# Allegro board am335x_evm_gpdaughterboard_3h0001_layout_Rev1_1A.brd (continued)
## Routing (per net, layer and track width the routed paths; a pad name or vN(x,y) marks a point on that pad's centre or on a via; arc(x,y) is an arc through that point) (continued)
VDDSHV5: length 1.9
  TOP w0.121: R4.2 R8.2
VDDSHV6: length 16.9
  TOP w0.254: U2.24 v1(112.15,97.42) ; U2.1 121.35,94.89 v1(121.46,94.78) ; v1(119.04,89.06) 118.95,89.15 U2.42 ; U2.31 v1(114.55,91.99)
  TOP w0.305: U11.3 v1(60.55,78.71) ; U10.3 v1(60.43,83.28)
  TOP w0.381: 60.38,83.22 v1(60.43,83.28)
  TOP w0.635: v1(60.49,76.24) 60.87,75.86 R9.2 v1(59.61,75.1) ; v1(62.78,76.24) R5.2 v1(63.78,75.1) ; C40.1 60.38,83.22
  BOTTOM w0.635: v1(60.55,78.71) 60.62,78.78 C44.1 ; v1(119.04,89.06) 119.23,89.25 119.23,89.35 119.29,89.42 C14.1 ; C13.1 114.55,91.56 v1(114.55,91.99)
ACCEL_INT1: length 55.8
  TOP w0.121: v2(93.34,67.13) U43.L5 ; U9.11 78.9,93.26 79.39,92.77 v1(79.39,92.75)
  LY3 w0.102: v2(93.34,67.13) 93.41,67.13 93.89,67.6 94.53,67.6 94.78,67.86 94.78,68.36 94.44,68.7 88.81,68.7
  LY3 w0.121: v1(79.39,92.75) 79.83,92.31 79.83,71.1 82.22,68.7 88.81,68.7
ACCEL_INT2: length 53.8
  TOP w0.121: U9.9 65.12,92.26 v1(65.43,91.94) ; v2(94.34,67.13) U43.L6
  LY3 w0.121: v1(66.91,68.3) 66.91,78 65.43,79.47 v1(65.43,91.94)
  LY6 w0.102: 88.81,68.11 92.64,68.11 93.03,67.72 93.74,67.72 v2(94.34,67.13)
  LY6 w0.121: v1(66.91,68.3) 71.6,68.3 71.79,68.11 88.81,68.11
AM335X_ECAP0_IN_PWM0_OUT: length 65.8
  TOP w0.121: v2(101.34,77.13) U43.B12
  LY3 w0.102: v2(98.64,94.7) 98.51,94.83 98.51,95.76 98.55,95.8 98.55,98.88 97.7,99.73 97.7,102.24 97.35,102.6 97.35,102.96 97.61,103.22
  LY3 w0.121: J3.19 96.43,135.75 98.71,133.47 98.71,125.17 97.02,123.47 97.02,118.39 98.15,117.26 98.15,103.76 97.61,103.22
  LY6 w0.102: v2(101.34,77.13) 101.34,77.55 101.26,77.63 101.26,79.13
  LY6 w0.121: v1(99.34,84.05) 100.93,84.05 101.26,83.73 101.26,79.13
  BOTTOM w0.102: v2(98.64,94.7) 98.51,94.58 98.51,94.21
  BOTTOM w0.121: 98.51,94.21 98.51,84.87 v1(99.34,84.05)
AM335X_GPMC_A0: length 141.4
  TOP w0.102: 97.73,78.65 98.04,78.34 98.1,78.34 98.23,78.21 98.23,75.44 97.84,75.04 U43.D9
  TOP w0.121: v1(86.94,82.28) 87.06,82.28 87.25,82.47 90.33,82.47 93.07,79.73 96.64,79.73 97.73,78.65 ; J4.2 83.73,128.18 83.86,128.31 83.86,129.58 83.73,129.7 81.32,129.7 81.19,129.58 81.19,127.67 81.06,127.55 73.71,127.55 73.58,127.67 73.58,129.97 73.46,130.09 73.22,130.09 73.1,129.97 73.1,127.67 72.98,127.55 72.74,127.55 72.62,127.67 72.62,129.97 72.5,130.09 72.26,130.09 72.14,129.97 72.14,127.67 72.02,127.55 71.77,127.55 71.65,127.67 71.65,129.97 71.53,130.09 71.29,130.09 71.17,129.97 71.17,127.67 71.05,127.55 70.81,127.55 70.69,127.67 70.69,129.97 70.57,130.09 70.33,130.09 70.21,129.97 70.21,127.67 70.09,127.55 69.63,127.55 69.51,127.67 69.51,130.95 69.38,131.07 67.42,131.07 67.3,131.2 67.3,133.51 67.17,133.64 66.94,133.64 66.82,133.51 66.82,131.2 66.7,131.07 66.45,131.07 66.33,131.2 66.33,132 66.21,132.12 65.97,132.12 65.85,132 65.85,131.2 65.73,131.07 65.49,131.07 65.37,131.2 65.37,132 65.25,132.12 65.01,132.12 64.89,132 64.89,131.2 64.77,131.07 64.52,131.07 64.4,131.2 64.4,131.86 64.28,131.99 64.05,131.99 63.92,131.86 63.92,131.36 v1(63.65,131.09)
  LY6 w0.121: v1(75.03,82.47) 75.22,82.28 v1(86.94,82.28)
  BOTTOM w0.121: v1(63.65,131.09) 66.96,127.78 66.96,105.21 68.34,103.83 68.34,86.17 68.66,85.86 71.65,85.86 v1(75.03,82.47)
AM335X_GPMC_A1: length 63.3
  TOP w0.121: v2(99.34,75.12) U43.D10
  LY3 w0.102: v2(99.34,75.12) 98.97,75.12 98.07,76.03 98.07,78.65
  LY3 w0.121: v1(95.92,116.82) 95.92,116.24 96.29,115.87 96.29,113.53 95.71,112.95 95.71,100.7 96.22,100.2 96.22,96.26 96.68,95.8 96.68,93.13 97.62,92.19 97.62,89.39 98.07,88.95 98.07,78.65
  LY6 w0.121: v1(95.92,116.82) 91.03,116.82 86.27,121.58 86.27,126.91 J4.4
AM335X_GPMC_A2: length 63.2
  TOP w0.121: v2(100.34,75.12) U43.D11
  LY3 w0.102: 98.34,78.65 98.34,76.24 98.97,75.6 99.86,75.6 100.34,75.13 v2(100.34,75.12)
  LY3 w0.121: 98.34,78.65 98.34,89.17 97.9,89.6 97.9,92.42 96.94,93.38 96.94,96.43 96.46,96.9 96.46,100.46 96.18,100.75 96.18,113.07 96.54,113.43 96.54,116.94 95.96,117.52 v1(95.93,117.52)
  LY6 w0.121: v1(95.93,117.52) 95.93,117.52 95.47,117.06 91.42,117.06 88.56,119.93 88.56,127.16 J4.6
AM335X_GPMC_A3: length 63.1
  TOP w0.121: v2(101.34,75.12) U43.D12
  LY3 w0.121: v1(99.03,116.94) 99.22,116.75 99.22,106.97 101.64,104.56 101.64,100.62 101.99,100.27 101.99,92.72 101.58,92.31 101.58,90.21 101.64,90.15 v1(101.64,85.13)
  LY6 w0.102: 101.64,78.65 101.64,78.27 101.94,77.96 101.94,76.15 101.34,75.54 v2(101.34,75.12)
  LY6 w0.121: v1(101.64,85.13) 101.64,78.65 ; J4.8 90.08,128.05 91.22,126.91 91.22,118.53 91.99,117.77 95.29,117.77 95.54,118.02 97.95,118.02 v1(99.03,116.94)
AM335X_GPMC_A4: length 101.3
  TOP w0.121: v1(112.33,130.49) 111.8,129.96 99.68,129.96 98.87,129.15 93.89,129.15 92.92,128.18 J4.10 ; U43.D13 v2(102.33,75.12) ; U4.41 v1(118.55,105.6)
  LY6 w0.102: v2(102.33,75.12) 102.33,75.54 102.73,75.94 102.73,78.29 102.44,78.58 102.44,78.65
  LY6 w0.121: v1(120.66,85.86) 120.33,85.53 113.98,85.53 113.34,86.17 104.92,86.17 102.44,83.7 102.44,78.65 ; v1(112.33,130.49) 112.33,130.11 111.82,129.6 111.82,119.44 118.3,112.97 118.3,108.67 118.55,108.42 v1(118.55,105.6)
  BOTTOM w0.121: v1(118.55,105.6) 118.55,104.74 118.86,104.43 118.86,104.43 119.16,104.13 119.16,104.13 119.67,103.62 119.67,99.33 120.59,98.41 120.59,97.26 120.57,97.24 120.57,92.2 120.48,92.11 120.48,90.18 120.99,89.67 120.99,86.19 v1(120.66,85.86)
AM335X_GPMC_A5: length 171
  TOP w0.121: U4.40 118.15,102 117.39,101.24 109.33,101.24 v1(109.14,101.43) 108.5,102.07 108.5,103.92 107.73,104.69 98.84,104.69 98.24,105.29 92.67,105.29 91.91,106.05 68.97,106.05 68.49,105.57 66.49,105.57 v1(66.01,106.05) ; U43.D14 v2(103.33,75.12) ; v1(66.03,135.29) 67.04,134.28 67.73,134.28 67.98,134.02 67.98,131.86 68.24,131.61 69.76,131.61 70.14,131.23 70.14,130.85 70.4,130.59 76.36,130.59 76.49,130.47 76.49,128.43 76.62,128.31 76.87,128.31 76.99,128.43 76.99,130.22 77.11,130.34 77.35,130.34 77.47,130.22 77.47,128.43 77.59,128.31 77.83,128.31 77.95,128.43 77.95,130.22 78.07,130.34 78.31,130.34 78.43,130.22 78.43,128.43 78.55,128.31 78.8,128.31 78.92,128.43 78.92,130.22 79.04,130.34 79.28,130.34 79.4,130.22 79.4,128.43 79.52,128.31 80.43,128.31 80.56,128.43 80.56,130.85 80.68,130.97 88.76,130.97 88.88,130.85 88.88,127.68 89.06,127.5 89.58,126.98 95.03,126.98 95.16,127.11 J4.12
  LY3 w0.121: v1(109.14,101.43) 109.58,100.99 109.58,84.1 109.33,83.85 109.33,82.66 109.38,82.61 v1(109.38,80.14) ; v1(66.03,135.29) 66.01,135.28 v1(66.01,106.05)
  LY6 w0.102: v2(103.33,75.12) 103.94,75.73 104.5,75.73 104.73,75.96 104.73,76.67 104.93,76.88 104.93,77.35 105.22,77.63 105.52,77.63 105.85,77.96 105.85,78.62 105.89,78.65
  LY6 w0.121: 105.89,78.65 107.38,80.14 v1(109.38,80.14)
AM335X_GPMC_A6: length 229.2
  TOP w0.121: U43.E6 v2(94.34,74.12) ; U4.38 117.35,104.18 117.27,104.26 v1(117.27,104.99) ; J4.16 99.16,127.1 96.16,127.1 95.8,126.74 89.48,126.74 88.56,127.66 88.56,129.7 87.92,130.34 80.94,130.34 80.81,130.21 80.81,128.18 80.68,128.05 76.3,128.05 76.18,128.17 76.18,130.22 76.06,130.34 75.82,130.34 75.7,130.22 75.7,128.05 75.57,127.93 75.34,127.93 75.21,128.05 75.21,130.22 75.09,130.34 74.85,130.34 74.73,130.22 74.73,128.18 74.6,128.05 74.38,128.05 74.25,128.18 74.25,130.22 74.13,130.34 70.01,130.34 69.76,130.59 69.76,131.1 69.51,131.36 67.98,131.36 67.6,131.74 67.6,133.64 67.35,133.9 63.97,133.9 v1(63.07,134.8)
  LY3 w0.102: v2(94.34,74.12) 93.73,74.73 93.06,74.73 92.93,74.86 92.93,75.42 92.62,75.73 92.37,75.73 92.37,75.72 92.18,75.72 91.94,75.96 91.94,76.44 91.65,76.73 91.08,76.73 90.74,77.07 90.74,78.65
  LY3 w0.121: v1(63.07,134.8) 64.3,133.56 v1(64.3,111.73) ; v1(80.45,135.92) 80.45,113.91 81.15,113.21 81.15,86.32 82.53,84.94 84.03,84.94 84.54,85.46 85.95,85.46 86.45,84.96 86.45,84.28 88.26,82.47 89.66,82.47 90.2,81.93 90.2,81.5 90.86,80.85 90.86,78.77 90.74,78.65
  LY6 w0.121: v1(80.45,135.92) 79.33,134.8 v1(63.07,134.8) ; v1(117.27,104.99) 113,109.26 95.76,109.26 93.55,111.46 73.78,111.46 73.06,112.18 64.75,112.18 v1(64.3,111.73)
AM335X_GPMC_A7: length 101.2
  TOP w0.121: v2(95.34,74.12) U43.E7 ; U4.37 116.95,101.96 v1(116.75,101.76) ; J4.18 104.27,129.67 118.39,129.67 v1(118.43,129.63)
  LY3 w0.102: v2(95.34,74.12) 95.93,74.72 95.93,78.58 95.91,78.58 95.88,78.61 95.88,78.65
  LY3 w0.121: 95.88,78.65 95.88,95.16 95.47,95.57 95.47,99.54 94.65,100.37 v1(94.65,102.78)
  LY6 w0.121: v1(116.75,101.76) 115.61,101.76 114.81,102.56 108.02,102.56 106.4,104.18 96.05,104.18 v1(94.65,102.78)
  BOTTOM w0.121: v1(116.75,101.76) 116.58,101.93 116.58,105.27 116.88,105.58 116.88,109.46 116.58,109.77 116.58,109.81 115.99,110.4 115.99,119.04 115.73,119.29 115.73,122.08 118.43,124.78 118.43,129.32 118.43,129.33 v1(118.43,129.63)
AM335X_GPMC_A8: length 98.8
  TOP w0.121: J4.22 107.86,128.15 109.31,126.71 v1(121.98,126.71) ; U4.47 120.95,104.11 121.27,104.43 v1(122.53,104.43) ; v2(96.34,74.12) U43.E8
  LY6 w0.102: v2(96.34,74.12) 96.34,73.71 96.73,73.31 96.73,73.13 97.13,72.73 97.68,72.73 98.25,73.3 98.25,78.65
  LY6 w0.121: 98.25,78.65 98.25,85.2 99.47,86.42 113.44,86.42 113.98,85.89 119.97,85.89 123.79,89.7 123.79,103.19 122.54,104.43 v1(122.53,104.43) 122.53,105.28 122.46,105.35 122.46,107.62 122.53,107.68 122.53,108.04 122.46,108.1 122.46,126.22 v1(121.98,126.71)
AM335X_GPMC_A9: length 93.9
  TOP w0.121: U4.46 120.55,104.19 121.37,105.02 v1(122.01,105.02) ; J4.24 111.52,129.3 116.8,129.3 117.39,128.71 v1(119.29,128.71) ; v2(97.34,74.12) U43.E9
  LY6 w0.102: v2(97.34,74.12) 97.67,74.12 98,74.46 98,78.52 97.88,78.65
  LY6 w0.121: 97.88,78.65 97.88,85.51 99.1,86.73 113.48,86.73 114.08,86.13 119.84,86.13 123.42,89.71 123.42,102.89 122.01,104.3 v1(122.01,105.02) 121.53,105.5 121.53,112.08 118.96,114.64 118.96,128.38 v1(119.29,128.71)
AM335X_GPMC_A10: length 86.3
  TOP w0.102: 106.91,103.01 107.5,102.42
  TOP w0.121: v1(99.59,103.67) 100.96,103.67 101.6,103.04 106.88,103.04 106.91,103.01 ; v1(120.15,105.55) 120.15,105.49 119.65,104.99 119.65,104.28 119.75,104.17 U4.44 119.75,101.81 118.86,100.93 108.99,100.93 107.5,102.42 ; v2(99.34,74.12) U43.E10 ; v1(120,127.27) 119.57,127.27 119.37,127.06 114.01,127.06 112.94,128.13 J4.26
  LY3 w0.102: 99.59,103.01 99.59,95.07 99.33,94.82 99.33,94.48 99.54,94.28 99.54,94.21
  LY3 w0.121: v1(99.69,80.68) 99.69,81.19 99.88,81.38 99.88,92.7 99.54,93.04 99.54,94.21 ; v1(99.59,103.67) 99.59,103.01
  LY6 w0.102: v2(99.34,74.12) 99.34,74.54 99.74,74.95 99.74,78.65
  LY6 w0.121: v1(99.69,80.68) 99.69,80.31 99.85,80.14 99.85,79.06 99.74,78.95 99.74,78.65
  BOTTOM w0.121: v1(120,127.27) 120,109.26 119.65,108.9 119.65,107.35 120.15,106.85 v1(120.15,105.55)
AM335X_GPMC_A11: length 83.9
  TOP w0.121: v2(100.34,74.12) U43.E11 ; U4.43 v1(119.35,105.57)
  LY3 w0.102: 107.86,69.82 107.71,69.67 105.09,69.67 104.71,70.05 v1(104.34,70.05)
  LY3 w0.121: 107.86,69.82 108.24,70.2 110.97,70.2 111.31,69.87 v1(111.75,69.87) ; v1(116.39,120.67) 116.39,125.21 116.43,125.25 116.43,127.23 J4.28
  BOTTOM w0.102: v1(104.34,70.05) 103.85,70.53 101.33,70.53 100.93,70.93 100.93,72.25 100.49,72.68 100.11,72.68 99.86,72.94 99.86,73.65 v2(100.34,74.12)
  BOTTOM w0.121: v1(111.75,69.87) 111.75,70.52 121.39,80.16 121.39,92.14 120.82,92.72 120.82,97.14 120.84,97.16 120.84,98.54 119.95,99.43 119.95,103.8 119.35,104.41 v1(119.35,105.57) 119.35,109.78 119.48,109.91 119.48,110.38 119.35,110.51 119.35,117.71 v1(116.39,120.67)
AM335X_GPMC_AD0: length 111.7
  TOP w0.121: v1(95.22,142.72) U23.6
  LY3 w0.121: v1(34.33,142.28) 34.77,141.84 34.77,141.21 34.33,140.76 34.33,128.43 32.68,126.78 31.91,126.78 31.34,126.21 31.34,117.25 31.83,116.75 31.83,104.56 31.96,104.43 32.55,104.43 32.68,104.56 32.68,105.19 32.8,105.32 35.09,105.32 35.22,105.19 35.22,104.18 35.09,104.05 J1.17
  LY6 w0.121: v1(34.33,142.28) 35.16,142.28 35.34,142.46 80.85,142.46 81.54,141.77 87.28,141.77 87.41,141.9 87.41,142.59 87.54,142.72 89.95,142.72 90.08,142.59 90.08,141.9 90.21,141.77 90.59,141.77 90.72,141.9 90.72,142.59 90.84,142.72 92.87,142.72 93,142.59 93,142.15 93.13,142.02 93.51,142.02 93.64,142.15 93.64,142.59 93.76,142.72 v1(95.22,142.72)
AM335X_GPMC_AD1: length 112.6
  TOP w0.121: U23.7 v1(96.16,143.44)
  LY3 w0.121: v1(34.33,143.04) 35.02,142.35 35.02,141.03 34.9,140.92 34.9,128.63 31.59,125.31 31.59,117.79 32.43,116.95 32.43,111.57 33.18,110.81 33.18,108.62 33.69,108.11 34.71,108.11 35.09,107.73 37.76,107.73 37.88,107.61 37.88,105.32 37.76,105.19 35.6,105.19 J1.15
  LY6 w0.121: v1(96.16,143.44) 95,143.44 94.54,142.98 86.95,142.98 85.88,144.06 75.98,144.06 74.97,143.04 36.86,143.04 36.72,143.17 36.3,143.17 36.13,143.35 35.44,143.35 35.13,143.04 v1(34.33,143.04)
AM335X_GPMC_AD2: length 112.5
  TOP w0.121: v1(91.73,141.9) 92,142.17 U23.1
  LY3 w0.121: J1.13 35.34,107.99 37.63,107.99 37.76,108.11 37.76,110.34 37.63,110.46 33.88,110.46 32.68,111.67 32.68,117.05 31.84,117.89 31.84,123.53 32.93,124.62 32.93,126.02 33.18,126.28 37.76,126.28 39.03,127.55 39.03,130.59 38.77,130.85 38.14,130.85 38.01,130.97 38.01,131.74 38.14,131.86 38.9,131.86 39.03,131.99 39.03,135.17 38.9,135.29 38.26,135.29 38.14,135.42 38.14,136.31 38.26,136.44 38.9,136.44 39.03,136.56 39.03,138.59 38.9,138.72 35.85,138.72 35.15,139.42 35.15,140.82 35.64,141.3 v1(35.64,141.83)
  LY6 w0.121: v1(91.73,141.9) 91.22,141.9 90.79,141.47 81.58,141.47 81.55,141.5 81.46,141.5 80.81,142.14 78.77,142.14 78.77,142.15 78.4,142.15 78.4,142.14 37.62,142.14 37.56,142.21 37.19,142.21 37.13,142.14 35.95,142.14 v1(35.64,141.83)
AM335X_GPMC_AD3: length 112.5
  TOP w0.121: v1(92.49,141.01) 93,141.52 U23.3
  LY3 w0.121: J1.11 35.6,111.67 35.72,111.8 35.72,113.07 35.6,113.19 33.06,113.19 32.93,113.32 32.93,117.64 32.79,117.78 32.3,117.78 32.17,117.91 32.17,123.48 32.3,123.61 33.06,123.61 33.18,123.74 33.18,125.77 33.31,125.89 37.63,125.89 37.76,125.77 37.76,123.86 37.88,123.74 38.52,123.74 38.65,123.86 38.65,126.5 39.28,127.13 39.28,138.72 39.03,138.98 35.98,138.98 35.62,139.34 v1(35.62,140.56)
  LY6 w0.121: v1(92.49,141.01) 92.49,139.05 91.53,138.09 71.92,138.09 71.79,138.21 71.79,139.66 71.67,139.79 71.03,139.79 70.9,139.66 70.9,138.98 70.78,138.85 69.89,138.85 69.76,138.98 69.76,139.66 69.63,139.79 35.74,139.79 35.62,139.92 v1(35.62,140.56)
AM335X_GPMC_AD4: length 108.8
  TOP w0.121: R255.2 83.67,143.61 v1(83.48,143.61)
  LY3 w0.121: J1.9 35.47,114.21 35.6,114.34 35.6,115.61 35.47,115.73 33.38,115.73 33.25,115.86 33.25,118.02 33.12,118.15 32.55,118.15 32.42,118.27 32.42,123.23 32.55,123.35 38.52,123.35 38.9,123.74 38.9,126.4 39.53,127.04 39.53,146.98 39.41,147.1 38.26,147.1 38.14,146.98 38.14,143.29 38.4,143.03 38.62,143.03 38.89,142.76 38.89,139.76 38.49,139.36 36.49,139.36 36.11,139.74 36.11,142.53 35.73,142.91 v1(35.72,142.91)
  LY6 w0.121: v1(35.72,142.91) 36.42,142.91 36.61,142.72 75.41,142.72 76.3,143.61 v1(83.48,143.61)
AM335X_GPMC_AD5: length 107
  TOP w0.121: R257.2 86.07,144.26 v1(86.7,144.26)
  LY3 w0.121: v1(36.49,143.61) 36.49,142.72 36.35,142.59 36.35,139.86 36.48,139.74 38.52,139.74 38.65,139.86 38.65,142.66 38.52,142.79 38,142.79 37.88,142.91 37.88,147.74 38,147.87 39.67,147.87 39.79,147.74 39.79,126.78 39.67,126.66 39.53,126.66 39.17,126.29 39.17,123.37 38.9,123.1 32.94,123.1 32.81,122.97 32.81,119.03 33.69,118.15 34.07,118.15 34.2,118.02 J1.7
  LY6 w0.121: v1(86.7,144.26) 86.21,144.26 86.02,144.45 75.22,144.45 74.07,143.29 38.26,143.29 37.94,143.61 v1(36.49,143.61)
AM335X_GPMC_AD6: length 98.5
  TOP w0.121: R256.2 78.4,144.56 77.63,143.8 v1(77.63,141.7)
  LY3 w0.121: v1(37.38,141.77) 36.87,141.77 36.74,141.64 36.74,140.37 36.87,140.25 38.26,140.25 38.39,140.37 38.39,142.4 38.26,142.53 37.76,142.53 37.63,142.66 37.63,149.64 37.76,149.77 39.92,149.77 40.04,149.64 40.04,126.53 39.78,126.27 39.69,126.27 39.41,126 39.41,123.1 39.16,122.85 33.18,122.85 33.06,122.72 33.06,119.42 33.18,119.29 J1.5
  LY6 w0.121: v1(77.63,141.7) 40.62,141.7 40.55,141.77 v1(37.38,141.77)
AM335X_GPMC_AD7: length 97.5
  TOP w0.121: v1(80.05,141.13) 80.05,143.89 80.68,144.52 R258.2
  LY3 w0.121: J1.3 34.2,120.43 34.33,120.31 39.53,120.31 39.66,120.43 39.66,125.89 39.79,126.02 40.17,126.02 40.3,126.15 40.3,150.28 40.17,150.41 37.5,150.41 37.38,150.28 37.38,142.4 37.5,142.28 38.01,142.28 38.14,142.15 38.14,141.01 38.01,140.88 v1(37.38,140.88)
  LY6 w0.121: v1(37.38,140.88) 39.53,140.88 39.65,141 79.53,141 79.67,141.13 v1(80.05,141.13)
AM335X_GPMC_AD8: length 107.9
  TOP w0.121: v2(103.33,63.13) U43.R14
  LY3 w0.102: 103.16,59.6 102.94,59.82 102.94,62.3 103.33,62.69 v2(103.33,63.13) ; 34.91,80.17 J5.11
  LY3 w0.121: v1(103.16,51.6) 103.16,53.8 102.99,53.97 102.99,55.59 102.85,55.73 102.85,56.1 103.16,56.41 103.16,59.6 ; v1(38.14,53.5) 38.14,65.19 35.47,67.86 35.47,79.79 35.09,80.17 34.91,80.17
  LY6 w0.121: v1(38.14,53.5) 38.57,53.94 41.51,53.94 42.58,52.87 57.31,52.87 58.33,51.85 102.4,51.85 102.65,51.6 v1(103.16,51.6)
AM335X_GPMC_AD9: length 108.8
  TOP w0.121: v2(102.33,63.13) U43.R13
  LY3 w0.102: 101.51,59.6 101.73,59.82 101.73,62.45 102.33,63.06 v2(102.33,63.13) ; 32.04,78.9 J5.14
  LY3 w0.121: 32.04,78.9 31.79,78.9 31.41,78.52 31.41,70.9 37.38,64.93 37.38,53.44 36.87,52.93 v1(36.87,52.62) ; 101.51,59.6 v1(101.51,50.96)
  LY6 w0.121: v1(36.87,52.62) 41.31,52.62 42.69,51.24 57.72,51.24 57.82,51.34 58.7,51.34 58.71,51.35 101.13,51.35 v1(101.51,50.96)
AM335X_GPMC_AD10: length 111.4
  TOP w0.121: v2(101.34,63.13) U43.R12
  LY3 w0.102: 100.73,59.58 100.73,62.47 101.34,63.07 v2(101.34,63.13) ; 36.49,84.49 J6.4
  LY3 w0.121: v1(99.73,50.84) 100.62,51.73 100.62,59.47 100.73,59.58 ; 36.49,84.49 35.72,83.73 35.72,68.11 38.58,65.25 38.58,52.87 38.14,52.43 v1(38.14,52.11)
  LY6 w0.121: v1(38.14,52.11) 38.65,51.6 41.06,51.6 41.91,50.75 58.4,50.75 58.49,50.84 97.83,50.84 98.27,50.39 99.29,50.39 v1(99.73,50.84)
AM335X_GPMC_AD11: length 111.4
  TOP w0.121: v2(100.34,63.13) U43.R11
  LY3 w0.102: J6.3 39.36,84.42 ; v2(100.34,63.13) 100.34,63 99.73,62.39 99.73,59.85 99.61,59.73 99.61,59.6
  LY3 w0.121: 39.36,84.42 40.11,83.66 40.11,51.28 39.07,50.25 v1(39.03,50.25) ; v1(98.59,49.57) 98.21,49.95 98.21,52.74 99.61,54.14 99.61,59.6
  LY6 w0.121: v1(39.03,50.25) 58.89,50.25 58.97,50.33 97.45,50.33 98.21,49.57 v1(98.59,49.57)
AM335X_GPMC_AD12: length 105.2
  TOP w0.121: v2(99.34,63.13) U43.R10
  LY3 w0.102: J5.13 34.84,78.9 34.91,78.83 ; 98.94,59.82 98.94,62.29 99.34,62.68 v2(99.34,63.13)
  LY3 w0.121: 98.94,59.82 99.16,59.6 99.16,54.07 97.19,52.11 v1(97.19,49.89) ; v1(38.14,50.2) 37.7,50.64 37.7,65.12 35.22,67.59 35.22,78.52 34.91,78.83
  LY6 w0.121: v1(97.19,49.89) 94.84,49.89 94.72,50 41.75,50 41.55,49.81 38.53,49.81 v1(38.14,50.2)
AM335X_GPMC_AD13: length 111.1
  TOP w0.121: v2(102.33,64.13) U43.P13
  LY3 w0.102: J6.6 36.36,83.98 36.23,83.86 ; 102.15,59.6 101.94,59.8 101.94,62.29 102.17,62.52 102.52,62.52 102.74,62.73 102.74,63.28 102.33,63.68 v2(102.33,64.13)
  LY3 w0.121: v1(39.03,53.5) 39.03,65.23 35.98,68.28 35.98,83.61 36.23,83.86 ; 102.15,59.6 v1(102.15,51.35)
  LY6 w0.121: v1(39.03,53.5) 41.45,53.5 42.33,52.62 57.05,52.62 58.07,51.6 101.51,51.6 101.76,51.35 v1(102.15,51.35)
AM335X_GPMC_AD14: length 111.6
  TOP w0.121: v2(101.34,64.13) U43.P12
  LY3 w0.102: v2(101.34,64.13) 101.34,64.09 101.76,63.66 101.76,62.78 101.51,62.52 101.17,62.52 100.94,62.29 100.94,59.95 101.13,59.76 101.13,59.6 ; J6.5 39.28,83.98 39.36,83.91
  LY3 w0.121: v1(100.62,50.84) 101.13,51.35 101.13,59.6 ; 39.36,83.91 39.86,83.4 39.86,51.93 v1(39.03,51.09)
  LY6 w0.121: v1(100.62,50.84) 99.86,50.08 98.21,50.08 97.7,50.58 58.58,50.58 58.5,50.5 41.78,50.5 41.19,51.09 v1(39.03,51.09)
AM335X_GPMC_AD15: length 108.8
  TOP w0.121: v2(100.34,64.13) U43.P11
  LY3 w0.102: J6.8 36.49,82.71 ; v2(100.34,64.13) 100.34,64.08 100.75,63.66 100.75,62.78 100.49,62.52 100.17,62.52 99.94,62.29 99.94,59.77 100.11,59.6
  LY3 w0.121: 100.11,59.6 100.11,51.98 v1(98.97,50.84) ; v1(39.03,52.11) 39.47,52.55 39.47,65.25 36.23,68.49 36.23,82.46 36.49,82.71
  LY6 w0.121: v1(39.03,52.11) 41.31,52.11 42.43,50.99 58.2,50.99 58.3,51.09 97.95,51.09 98.21,50.84 v1(98.97,50.84)
AM335X_GPMC_ADVN_ALE: length 90.5
  TOP w0.121: v1(82.94,100.27) 81.26,101.95 58.9,101.95 57.95,101 v1(46.96,101) ; v2(95.34,72.13) U43.G7
  LY3 w0.102: 88.81,69.2 91.97,69.2 92.73,69.96 92.73,70.12 93.13,70.52 94.33,70.52 94.73,70.92 94.73,71.52 v2(95.34,72.13)
  LY3 w0.121: v1(85.55,69.82) 86.17,69.2 88.81,69.2
  BOTTOM w0.121: v1(82.94,100.27) 84.13,100.27 85.84,98.55 85.84,97.36 85.76,97.28 85.76,89.29 85.84,89.2 85.84,88.79 85.76,88.7 85.76,86.63 85.57,86.44 85.57,83.99 85.14,83.56 85.14,70.67 85.55,70.26 v1(85.55,69.82) ; J2.26 46.96,96.49 v1(46.96,101)
AM335X_GPMC_BE0N_CLE: length 60.8
  TOP w0.102: 88.81,71.65 U43.H1
  TOP w0.121: 88.29,72.17 88.3,72.17 88.81,71.67 88.81,71.65 88.29,72.17 ; 88.29,72.17 86.78,72.17 85.52,73.43 83.49,73.43 82.67,74.25 67.45,74.25 67.35,74.14 65.13,74.14 64.69,73.7 v1(64.68,73.7)
  BOTTOM w0.121: v1(64.68,73.7) 64.17,74.21 64.17,74.87 64.22,74.92 64.22,76.44 63.22,77.45 63.22,78.89 61.56,80.55 61.56,85.5 55.2,91.86 44.87,91.86 J2.28
AM335X_GPMC_BE1N: length 85.1
  TOP w0.121: v1(82.59,77) 81.57,78.02 76.49,78.02 74.46,80.05 v1(71.92,80.05) ; v2(89.34,70.13) U43.J1
  LY3 w0.102: 88.81,70.13 v2(89.34,70.13)
  LY3 w0.121: 88.81,70.13 88.44,70.13 88.17,70.4 85.74,70.4 84.67,71.46 84.67,74.92 v1(82.59,77) ; J3.2 73.57,139.23 72.05,137.71 72.05,111.54 72.63,110.95 72.63,106.9 72.76,106.77 72.76,91.69 72.3,91.22 72.3,80.43 v1(71.92,80.05)
AM335X_GPMC_CLK: length 72.4
  TOP w0.121: v1(71.73,84.41) 70.61,84.41 69.38,85.64 67.86,85.64 65.7,87.79 50.96,87.79 49.95,88.81 49.95,92.62 47.54,95.03 43.09,95.03 41.82,96.3 J2.23 ; v2(92.34,71.13) U43.H4
  LY6 w0.121: v1(71.73,84.41) 72.07,84.75 81.84,84.75 82.35,84.23 89.64,84.23 90.26,84.85 v1(90.26,84.85)
  BOTTOM w0.102: 90.73,78.65 90.73,72.15 91.36,71.52 91.52,71.52 91.92,71.13 v2(92.34,71.13)
  BOTTOM w0.121: v1(90.26,84.85) 89.93,84.52 89.93,80.45 90.19,80.2 90.41,80.2 90.73,79.88 90.73,78.65
AM335X_GPMC_CS0N: length 69
  TOP w0.121: v1(81.39,83.36) 80.78,83.97 70.41,83.97 69,85.38 67.73,85.38 65.7,87.41 50.35,87.41 49.46,88.3 49.46,92.09 48.81,92.75 42.96,92.75 J2.25 ; v2(93.34,71.13) U43.H5
  LY3 w0.102: 88.81,70.73 92.5,70.73 92.89,71.13 v2(93.34,71.13)
  LY3 w0.121: 88.81,70.73 85.8,70.73 84.91,71.61 84.91,75.86 81.39,79.38 v1(81.39,83.36)
AM335X_GPMC_CS1N: length 112.5
  TOP w0.121: U23.9 v1(96.17,144.44)
  LY3 w0.121: J1.21 31.34,101.83 31.34,116.44 30.84,116.93 30.84,126.48 33.82,129.45 v1(33.82,143.61)
  LY6 w0.121: v1(96.17,144.44) 95.34,144.44 94.17,143.27 89.9,143.27 88.47,144.7 74.47,144.7 73.31,143.54 39.41,143.54 38.9,144.06 34.26,144.06 v1(33.82,143.61)
AM335X_GPMC_CS2N: length 112.3
  TOP w0.121: v1(94.02,141.01) 93.51,141.52 U23.4
  LY3 w0.121: J1.19 35.6,101.51 35.72,101.64 35.72,102.91 35.6,103.03 31.71,103.03 31.59,103.16 31.59,116.65 31.09,117.15 31.09,126.34 31.79,127.04 32.42,127.04 34.07,128.69 34.07,140.88 34.33,141.13 v1(34.33,141.39)
  LY6 w0.121: v1(94.02,141.01) 93.51,141.52 92.74,141.52 92.68,141.45 91.6,141.45 91.36,141.22 85.85,141.22 85.64,141.01 81.25,141.01 80.68,141.58 79.73,141.58 79.41,141.26 37.62,141.26 37.56,141.33 35.66,141.33 34.96,140.63 33.57,140.63 33.44,140.75 33.44,141.26 33.57,141.39 v1(34.33,141.39)
AM335X_GPMC_CS3N: length 135.4
  TOP w0.121: v2(90.33,70.13) U43.J2
  LY3 w0.121: J3.4 74.84,138.34 74.84,136.44 72.88,134.48 72.88,107.12 73.06,106.95 73.06,91.47 72.61,91.03 72.61,75.28 71.67,74.33 71.67,65.32 71.79,65.19 73.06,65.19 73.19,65.32 73.19,86.27 73.32,86.4 73.7,86.4 73.82,86.27 73.83,85.38 73.83,70.26 73.95,70.14 v1(73.95,69.13)
  LY6 w0.102: v2(90.33,70.13) 89.88,70.58 88.81,70.58
  LY6 w0.121: v1(73.95,69.13) 74.39,69.57 77.58,69.57 78.34,70.33 78.83,70.33 79.63,69.53 83.02,69.53 83.46,69.98 83.46,70.07 83.97,70.58 88.81,70.58
AM335X_GPMC_OEN_REN: length 80.1
  TOP w0.121: v2(91.33,70.13) U43.J3
  LY3 w0.121: v1(84.17,70.13) 84.17,72.31 80.14,76.34 80.14,101.6 79.76,101.98 79.76,138.5 J3.6
  LY6 w0.102: 88.81,69.73 90.5,69.73 90.89,70.13 v2(91.33,70.13)
  LY6 w0.121: v1(84.17,70.13) 84.61,70.13 84.81,70.33 88.23,70.33 88.36,70.2 88.36,70.19 88.81,69.73
AM335X_GPMC_WAIT: length 76
  TOP w0.121: v2(90.33,71.13) U43.H2 ; J2.19 42.84,100.49 59.89,100.49 60.52,99.86 v1(78,99.86)
  LY6 w0.102: 88.81,71.13 v2(90.33,71.13)
  LY6 w0.121: v1(81.57,72.55) 87.29,72.55 88.72,71.13 88.81,71.13
  BOTTOM w0.121: v1(81.57,72.55) 81.57,74.46 80.39,75.64 80.39,97.96 78.48,99.86 v1(78,99.86)
AM335X_GPMC_WEN: length 73
  TOP w0.102: U43.A2 90.84,77.63 90.84,78.65
  TOP w0.121: v1(81.32,78.78) 82.31,78.78 82.85,79.32 90.18,79.32 90.84,78.65
  LY3 w0.121: J3.8 80.01,138.43 80.01,105.93 80.8,105.14 80.8,79.22 81.24,78.78 v1(81.32,78.78)
AM335X_GPMC_WPN: length 86
  TOP w0.121: U43.H3 v2(91.33,71.13)
  LY3 w0.121: v1(54.01,97.95) 54.01,93.38 57.19,90.21 57.19,74.33 v1(58.08,73.44)
  LY6 w0.102: v2(91.33,71.13) 90.93,71.13 90.53,71.52 88.81,71.52
  LY6 w0.121: v1(54.01,97.95) 46.14,97.95 46.01,98.08 46.01,98.31 46.14,98.44 50.84,98.44 50.96,98.56 50.96,98.79 50.84,98.92 45.5,98.92 45.38,98.79 45.38,98.08 45.25,97.95 42.84,97.95 J2.21 ; v1(58.08,73.44) 58.71,72.81 60.36,72.81 60.65,73.1 67.82,73.1 68.53,73.82 77.01,73.82 77.81,73.01 83.02,73.01 83.22,72.81 87.41,72.81 88.7,71.52 88.81,71.52
AM335X_I2C0_SCL: length 156.7
  TOP w0.102: 39.36,78.29 37.86,78.29 J6.14
  TOP w0.121: U1.6 v1(43.98,85) 44.69,84.29 46.51,84.29 46.91,83.89 46.91,82.29 42.91,78.29 39.36,78.29 ; U43.M5 v2(93.34,66.13)
  LY3 w0.121: 84.11,37.25 84.11,36.23 84.49,35.85 88.18,35.85 89.32,36.99 89.32,39.3 87.94,40.68 85.15,40.68 77.89,47.94 77.89,56.91 86.37,65.39 86.37,65.71 v1(86.83,66.16) ; v1(43.98,85) 47.46,81.52 47.46,47.16 48.8,45.83 54.78,45.83 57.09,43.52 58.05,43.52 59.2,42.38 v1(59.2,36.3)
  LY6 w0.102: 88.81,65.57 92.78,65.57 v2(93.34,66.13)
  LY6 w0.121: 88.81,65.57 87.42,65.57 v1(86.83,66.16) ; v1(59.2,36.3) 84.01,36.3 84.11,36.4 84.11,37.25
AM335X_I2C0_SDA: length 169.3
  TOP w0.121: U43.M6 v2(94.34,66.13) ; 85.38,34.07 85.38,34.95 85.18,35.15 v1(59.79,35.15) ; v1(42,75.41) 47.39,75.41 48.02,76.04 v1(48.02,84.49) ; v1(43.98,86.27) U1.5
  LY3 w0.102: 88.81,64.93 89.65,64.93 90.28,65.57 94.02,65.57 94.34,65.89 v2(94.34,66.13)
  LY3 w0.121: v1(43.98,86.27) 46.25,86.27 v1(48.02,84.49) 48.02,46.96 48.66,46.32 55.6,46.32 59.79,42.13 v1(59.79,35.15) ; 88.81,64.93 86.26,64.93 78.14,56.8 78.14,48.05 85.25,40.93 88.04,40.93 89.57,39.4 89.57,36.74 88.3,35.47 86.02,35.47 85.38,34.84 85.38,34.07
  LY6 w0.102: 36.49,75.75 38.93,75.75 39.33,75.36 39.33,74.47 39.36,74.45 ; J5.15 34.91,77.63
  LY6 w0.121: 34.91,77.63 34.96,77.63 35.85,76.75 35.85,76.39 36.49,75.75 ; 39.36,74.45 39.86,74.45 40.82,75.41 v1(42,75.41)
AM335X_MCASP0_ACLKR: length 62.5
  TOP w0.121: v1(94.59,120.97) 97.69,120.97 99.08,122.36 100.43,122.36 102.78,124.71 J4.17 ; v2(97.34,73.12) U43.F9
  LY6 w0.102: v2(97.34,73.12) 97.34,73.22 96.76,73.8 96.76,74.36 97.07,74.66 97.43,74.66 97.73,74.96 97.73,78.3
  LY6 w0.121: 97.73,78.3 97.55,78.48 97.55,85.83 97.02,86.35 v1(96.53,86.35)
  BOTTOM w0.121: v1(96.53,86.35) 96.53,90.35 96.19,90.68 96.19,94.71 94.09,96.81 94.09,101.59 95.09,102.6 95.09,116.31 94.59,116.81 v1(94.59,120.97)
AM335X_MCASP0_ACLKX: length 73.9
  TOP w0.121: v2(101.34,74.12) U43.E12
  LY3 w0.102: v1(97.96,94.65) 97.96,94.79 97.74,95.01 97.74,97.27 97.29,97.72 97.29,102.31
  LY3 w0.121: 97.29,102.31 97.11,102.5 97.11,103.11 97.36,103.36 97.39,103.36 97.7,103.67 v1(97.7,116.82)
  LY6 w0.102: 100.07,78.65 99.94,78.52 99.94,74.92 100.34,74.52 100.52,74.52 100.92,74.12 v2(101.34,74.12)
  LY6 w0.121: v1(99.44,84.66) 98.99,84.66 98.89,84.56 98.89,82.39 99.17,82.12 99.69,82.12 100.13,81.68 100.13,78.71 100.07,78.65 ; v1(97.7,116.82) 97.26,116.37 89.72,116.37 87.95,118.15 83.48,118.15 82.46,119.16 J4.1
  BOTTOM w0.102: v1(97.96,94.65) 97.96,94.21
  BOTTOM w0.121: 97.96,94.21 97.96,84.14 99.1,83 99.56,83 99.82,83.25 99.82,84.29 v1(99.44,84.66)
AM335X_MCASP0_AHCLKR: length 56.4
  TOP w0.121: v2(96.34,73.12) U43.F8
  LY3 w0.102: 97.02,78.65 97.02,78.49 96.93,78.4 96.93,73.72 v2(96.34,73.12)
  LY3 w0.121: 97.02,78.65 97.02,88.57 96.13,89.47 96.13,95.26 95.72,95.67 95.72,99.73 95.22,100.24 95.22,110.34 94.83,110.73 94.83,114.5 95.47,115.15 95.47,115.86 95.03,116.3 v1(95.03,119.04)
  LY6 w0.121: v1(95.03,119.04) 95.72,119.04 96.61,119.93 96.61,124.55 J4.13
AM335X_MCASP0_AHCLKX: length 73.6
  TOP w0.121: v1(108.6,77.69) 109.81,77.69 110.32,78.2 110.32,79.6 111.97,81.25 112.88,81.25 114.26,82.63 v1(114.26,86.57) ; v2(101.34,73.12) U43.F12
  LY6 w0.102: 107.86,76.47 107.55,76.47 107.5,76.52 106.17,76.52 105.93,76.28 105.93,75.88 105.73,75.67 105.73,74.96 105.5,74.73 104.38,74.73 103.73,74.08 103.73,73.96 103.5,73.73 103.08,73.73 102.77,74.05 102.77,74.25 102.5,74.52 102.17,74.52 101.73,74.08 101.73,73.96 101.34,73.57 v2(101.34,73.12)
  LY6 w0.121: v1(108.6,77.69) 108.6,77.21 107.86,76.47 ; J4.27 118.48,122.64 118.48,114.07 121.2,111.35 121.2,104.51 123.03,102.67 123.03,89.71 119.9,86.57 v1(114.26,86.57)
AM335X_MCASP0_AXR0: length 70.4
  TOP w0.121: v2(95.34,73.12) U43.F7 ; v1(82.9,121.87) 84.57,123.53 87.97,123.53 J4.7
  LY6 w0.102: 88.81,78.65 89.88,78.65 90.73,77.8 90.73,76.13 91.13,75.73 93.62,75.73 93.94,75.41 93.94,74.92 94.14,74.71 94.65,74.71 94.91,74.46 94.91,73.55 v2(95.34,73.12)
  LY6 w0.121: 88.81,78.65 87.39,78.65 86.72,79.32 v1(82.09,79.32)
  BOTTOM w0.121: v1(82.9,121.87) 82.9,114.83 81.52,113.44 81.52,87.15 82.09,86.57 v1(82.09,79.32)
AM335X_MCASP0_AXR1: length 80.1
  TOP w0.121: v1(108.5,92.37) 111.29,92.37 111.35,92.43 121.18,92.43 121.9,93.15 121.9,96.23 121.73,96.4 121.73,97.28 119.69,99.32 v1(117.92,99.32) ; v2(100.34,73.12) U43.F11 ; J4.23 110.4,124.12 114.72,119.8 v1(116.37,119.8)
  BOTTOM w0.102: 107.86,78.52 107.86,78.02 107.58,77.73 107.07,77.73 106.73,77.39 106.73,76.96 106.38,76.62 101.26,76.62 100.88,76.24 100.88,73.7 100.34,73.16 v2(100.34,73.12)
  BOTTOM w0.121: v1(108.5,92.37) 107.86,91.73 107.86,90.87 108.11,90.61 108.11,78.78 107.86,78.52 ; v1(117.92,99.32) 117.19,100.04 117.19,102.34 116.83,102.7 116.83,105.17 116.99,105.33 117.13,105.47 117.13,109.67 116.37,110.43 v1(116.37,119.8)
AM335X_MCASP0_FSR: length 63.9
  TOP w0.121: v2(99.34,73.12) U43.F10
  LY3 w0.121: v1(101.95,124.52) 100.22,122.79 99.53,122.79 98.71,121.97 98.71,118.78 100.37,117.12 100.37,113.32 102.65,111.04 102.65,99.99 102.4,99.73 102.4,92.37 v1(102.02,91.99)
  LY6 w0.102: v2(99.34,73.12) 98.5,73.96 98.5,78.65
  LY6 w0.121: 98.5,78.65 98.5,84.82 v1(99.44,85.77) ; v1(101.95,124.52) 106.74,124.52 J4.21
  BOTTOM w0.121: v1(99.44,85.77) 101.7,88.02 101.7,91.66 v1(102.02,91.99)
AM335X_MCASP0_FSX: length 81
  TOP w0.121: v1(90.58,110.97) 96.72,110.97 99.83,107.86 v1(111.2,107.86) ; v2(102.33,74.12) U43.E13
  LY6 w0.102: 107.86,75.8 107.56,75.8 107.5,75.73 106.38,75.73 105.94,75.29 105.94,74.89 105.58,74.53 105.14,74.53 104.73,74.12 104.73,73.96 104.5,73.73 103.79,73.73 103.58,73.53 102.93,73.53 v2(102.33,74.12)
  LY6 w0.121: v1(111.57,83.73) 110.55,83.73 110.27,83.44 110.27,77.89 108.17,75.8 107.86,75.8
  BOTTOM w0.121: v1(111.2,107.86) 110.91,107.56 110.91,96.81 110.57,96.47 110.57,84.2 111.04,83.73 v1(111.57,83.73) ; J4.5 87.54,114.01 v1(90.58,110.97)
AM335X_MDIO_CLK: length 1.7
  TOP w0.121: TP79.1 J3.9
AM335X_MDIO_DATA: length 1.8
  TOP w0.121: TP78.1 J3.7
AM335X_MMC0_CLK: length 87.5
  TOP w0.121: v1(75.16,133.9) 75.16,137.47 75.95,138.27 84.93,138.27 J3.12 ; v2(92.34,78.13) U43.A4
  LY3 w0.121: v1(76.26,80.34) 76.26,89.3 75.76,89.79 75.76,107.98 75.32,108.43 75.32,133.29 75.16,133.45 v1(75.16,133.9)
  LY6 w0.102: 91.81,78.65 v2(92.34,78.13)
  LY6 w0.121: v1(76.26,80.34) 78.74,80.34 78.99,80.6 87.05,80.6 88.42,79.23 90.28,79.23 90.76,78.76 91.7,78.76 91.81,78.65
AM335X_MMC0_CMD: length 66.6
  TOP w0.121: v2(93.34,78.13) U43.A5
  LY3 w0.102: 93.34,78.65 v2(93.34,78.13)
  LY3 w0.121: 93.34,78.65 93.34,79.56 92.87,80.02 92.87,80.85 93.56,81.54 93.56,103.62 93.39,103.8 93.39,115.22 89.05,119.56 89.05,129.81 87.93,130.93 87.93,135.16 88.24,135.48 v1(88.24,135.92)
  BOTTOM w0.121: v1(88.24,135.92) 89.06,135.92 89.76,136.62 89.76,138.66 J3.14
AM335X_MMC0_DAT0: length 66.4
  TOP w0.121: J3.16 92.69,138.27 94.08,138.27 94.9,137.44 94.9,130.6 v1(95.67,129.83) ; v2(94.34,78.13) U43.A6
  LY3 w0.102: 94.14,78.65 94.28,78.52 94.34,78.52 v2(94.34,78.13)
  LY3 w0.121: 94.14,78.65 94.14,88.99 94.72,89.57 94.72,91.99 94.72,91.99 94.72,96.78 94.78,96.84 v1(94.78,97.41)
  BOTTOM w0.121: v1(94.78,97.41) 94.4,97.79 94.4,101.15 95.35,102.11 95.35,118.47 96.38,119.49 96.38,123.99 96.21,124.16 96.21,129.29 v1(95.67,129.83)
AM335X_MMC0_DAT1: length 64.5
  TOP w0.121: v2(96.34,78.13) U43.A8
  LY3 w0.102: v2(96.34,78.13) 96.34,78.65
  LY3 w0.121: 96.34,78.65 96.34,79.46 96.14,79.66 96.14,82.11 96.45,82.43 v1(96.45,82.87) ; v1(97.63,122.99) 99.14,124.5 99.14,134 98.02,135.12 98.02,138.66 J3.22
  BOTTOM w0.102: 97.01,94.21 97.01,103.01
  BOTTOM w0.121: v1(97.63,122.99) 97.01,122.36 97.01,103.01 ; 97.01,94.21 97.01,93 97.2,92.81 97.2,83.62 v1(96.45,82.87)
AM335X_MMC0_DAT2: length 66.5
  TOP w0.121: v2(97.34,78.13) U43.A9
  LY3 w0.102: 97.34,78.65 v2(97.34,78.13)
  LY3 w0.121: v1(96.76,91.54) 96.76,89.32 97.34,88.75 97.34,78.65 ; J3.24 100.41,138.51 v1(100.41,129.39)
  BOTTOM w0.102: 96.68,103.01 96.68,94.21
  BOTTOM w0.121: v1(100.41,129.39) 97.26,129.39 96.56,128.69 96.56,124.5 96.76,124.29 96.76,103.8 96.68,103.72 96.68,103.01 ; 96.68,94.21 96.68,92.62 96.76,92.54 v1(96.76,91.54)
AM335X_MMC0_DAT3: length 67.9
  TOP w0.121: v2(99.34,78.13) U43.A10
  LY3 w0.102: v2(99.34,78.13) 99.86,78.65 ; 101.69,94.21 101.69,100 101.31,100.38 101.03,100.38 100.74,100.66 100.74,103.01
  LY3 w0.121: 101.69,94.21 101.69,92.77 100.25,91.33 100.25,79.04 99.86,78.65 ; 100.74,103.01 100.74,103.81 98.46,106.09 98.46,117.38 98.15,117.69 98.15,122.73 98.77,123.35 99.86,123.35 101.19,124.68 101.19,128.49 102.65,129.96 102.65,138.21 J3.26
AM335X_RMII1_COL: length 76.4
  TOP w0.121: v2(106.34,78.13) U43.A17
  LY3 w0.121: J3.34 113.12,138.52 108.22,138.52 107.61,137.91 107.61,136.33 107.12,135.85 106.84,135.85 102.93,131.94 102.93,129.93 102.9,129.9 102.9,129.86 101.48,128.44 101.48,124.6 99.99,123.1 98.87,123.1 98.4,122.63 98.4,118.54 99.76,117.18 99.76,112.94 100.77,111.93 v1(100.77,110.15)
  BOTTOM w0.102: 103.92,94.4 103.92,95.1 103.36,95.67 102.4,95.67 101.64,96.43 101.64,98.59 100.74,99.49 100.74,102.97 100.77,103.01 ; 106.46,78.65 106.46,78.25 v2(106.34,78.13)
  BOTTOM w0.121: 106.46,78.65 106.46,89.15 104.61,91 104.61,93 103.92,93.69 103.92,94.4 ; 100.77,103.01 v1(100.77,110.15)
AM335X_RMII1_CRS: length 92
  TOP w0.121: v2(89.34,77.13) U43.B1
  BOTTOM w0.102: 88.81,77.13 v2(89.34,77.13)
  BOTTOM w0.121: 88.81,77.13 88.55,77.38 88.55,84.74 90.54,86.73 91.28,86.73 93.32,88.77 93.32,95.35 93.22,95.45 93.22,102.67 93.32,102.76 93.32,103.29 93.15,103.45 93.15,120.18 88.95,124.38 88.95,128.68 90.53,130.27 104.27,130.27 104.88,129.67 110.2,129.67 115.41,134.87 115.41,138.27 J3.36
AM335X_RMII1_REFCLK: length 76.9
  TOP w0.121: v2(93.34,77.13) U43.B5 ; J3.3 79.05,134.13 87.72,134.13 90.77,131.08 v1(90.77,129.83)
  LY3 w0.102: 92.73,78.65 92.73,77.73 v2(93.34,77.13)
  LY3 w0.121: v1(92.65,84.85) 92.6,84.81 92.6,84.17 92.31,83.88 92.31,79.16 92.73,78.74 92.73,78.65
  BOTTOM w0.121: v1(90.77,129.83) 91.35,129.25 91.35,122.72 93.4,120.67 93.4,103.67 93.64,103.43 93.64,102.45 93.53,102.35 93.53,95.76 93.64,95.66 93.64,89.02 95.35,87.31 95.35,85.19 95.01,84.85 v1(92.65,84.85)
AM335X_RMII1_RXCLK: length 85.4
  TOP w0.121: v2(89.34,75.12) U43.D1
  LY3 w0.121: v1(39.72,92.3) 39.72,113.77 J1.8
  LY6 w0.102: v2(89.34,75.12) 88.81,75.12
  LY6 w0.121: v1(39.72,92.3) 44.77,92.3 46.23,90.84 46.23,90.04 47.69,88.58 58.44,88.58 61.81,85.21 61.81,82.21 65.49,78.52 67.35,78.52 68.4,77.47 80.22,77.47 81.71,75.97 87.93,75.97 88.78,75.12 88.81,75.12
AM335X_RMII1_RXD0: length 71.1
  TOP w0.121: v2(94.34,77.13) U43.B6
  LY3 w0.121: J3.5 v1(78.65,118.88)
  LY6 w0.102: v2(94.34,77.13) 93.73,77.73 93.73,78.32 93.53,78.52 93.36,78.52 93.22,78.65
  LY6 w0.121: v1(81.39,84.24) 81.39,84.21 81.64,83.97 86.85,83.97 88.34,82.47 89.75,82.47 93.22,79 93.22,78.65
  BOTTOM w0.121: v1(81.39,84.24) 81.39,84.41 81.21,84.59 81.21,112.71 79.51,114.41 79.51,118.03 v1(78.65,118.88)
AM335X_RMII1_RXD1: length 80
  TOP w0.121: v2(92.34,74.12) U43.E4
  LY3 w0.102: v2(92.34,74.12) 91.73,74.73 89.17,74.73 88.94,74.96 88.94,74.97 88.81,75.1
  LY3 w0.121: 88.81,75.1 88.69,75.22 88.69,81.23 v1(89.24,81.78)
  LY6 w0.121: v1(89.24,81.78) 89.18,81.84 69.3,81.84 68.41,82.73 68.41,96.42 65.3,99.53 56.86,99.53 56.46,99.92 37.69,99.92 J1.22
AM335X_RMII1_RXD2: length 87.9
  TOP w0.121: v2(90.33,75.12) U43.D2
  LY3 w0.121: v1(39.13,97.51) 39.13,111.82 J1.10
  LY6 w0.102: 88.81,75.58 88.87,75.52 89.5,75.52 89.89,75.12 v2(90.33,75.12)
  LY6 w0.121: v1(39.13,97.51) 59.6,97.51 59.85,97.76 63.98,97.76 67.79,93.95 67.79,78.94 68.77,77.96 84.35,77.96 86.1,76.22 88.18,76.22 88.81,75.58
AM335X_RMII1_RXD3: length 91.3
  TOP w0.121: v2(90.33,76.13) U43.C2
  LY6 w0.102: 88.81,77.63 89.55,77.63 89.85,77.33 89.85,76.61 v2(90.33,76.13)
  LY6 w0.121: 88.81,77.63 86.73,77.63 86.15,78.21 68.9,78.21 68.24,78.87 v1(68.24,80.59)
  BOTTOM w0.121: v1(68.24,80.59) 68.24,83.76 67.86,84.15 67.86,100.85 60.97,107.73 60.97,116.3 56.91,120.37 38.2,120.37 J1.4
AM335X_RMII1_RXDV: length 84
  TOP w0.121: J1.14 40.42,105.45 40.42,100.74 41.05,100.11 53.59,100.11 v1(54.49,99.22) ; v2(92.34,75.12) U43.D4
  LY3 w0.102: v2(92.34,75.12) 91.93,75.12 91.33,75.72 90.17,75.72 89.73,76.17 89.73,78.52 89.71,78.55 89.71,78.88 89.73,78.9
  LY3 w0.121: v1(89.49,80.29) 89.49,79.85 89.73,79.61 89.73,78.9
  LY6 w0.121: v1(54.49,99.22) 65.24,99.22 68.1,96.36 68.1,81.69 68.95,80.85 88.04,80.85 88.6,80.29 v1(89.49,80.29)
AM335X_RMII1_RXERR: length 91.1
  TOP w0.121: v1(111.76,87.22) 96.77,87.22 95.35,85.8 v1(94.91,85.8) ; v2(91.33,77.13) U43.B3
  LY3 w0.102: v2(91.33,77.13) 91.33,77.57 90.94,77.96 90.94,78.29 91.23,78.58 91.23,78.65
  LY3 w0.121: J3.38 118.15,138.47 115.99,138.47 115.48,137.96 115.48,130.59 114.34,129.45 114.34,124.37 114.72,123.99 v1(114.72,120.56) ; 91.23,78.65 91.23,80.95 90.45,81.73 90.45,82.03 89.76,82.72 89.45,82.72 v1(89.26,82.91)
  BOTTOM w0.121: v1(111.76,87.22) 111.7,87.28 111.7,89.61 111.1,90.21 111.1,96.24 111.42,96.56 111.42,104.02 115.31,107.91 115.31,119.97 v1(114.72,120.56) ; v1(94.91,85.8) 90.58,85.8 89.82,85.03 89.82,84.76 89.26,84.2 v1(89.26,82.91)
AM335X_RMII1_TXCLK: length 94.1
  TOP w0.121: v2(91.33,76.13) U43.C3
  LY3 w0.121: v1(69.04,79.31) 68.68,79.67 68.68,82.07 68.27,82.48 v1(68.27,104.85)
  LY6 w0.102: 90.4,78.65 90.93,78.12 90.93,76.95 91.33,76.54 v2(91.33,76.13)
  LY6 w0.121: v1(68.27,104.85) v1(60.38,104.85) ; 90.4,78.65 90.07,78.99 87.66,78.99 86.36,80.29 79.67,80.29 78.69,79.31 v1(69.04,79.31)
  BOTTOM w0.121: v1(60.38,104.85) 59.91,105.31 59.91,113.24 54.9,118.26 37.77,118.26 J1.6
AM335X_RMII1_TXD0: length 76.3
  TOP w0.121: v2(91.33,74.12) U43.E3
  LY3 w0.102: v2(91.33,74.12) 90.94,74.52 88.81,74.52
  LY3 w0.121: v1(86.35,82.91) 87.05,82.91 88.32,81.64 88.32,74.97 88.77,74.52 88.81,74.52
  LY6 w0.121: v1(86.35,82.91) 72.55,82.91 70.2,85.26 70.2,95.01 65.38,99.84 59.02,99.84 58.3,100.56 37.69,100.56 J1.20
AM335X_RMII1_TXD1: length 72.6
  TOP w0.121: v2(90.33,74.12) U43.E2
  LY6 w0.102: v2(90.33,74.12) 88.81,74.12
  LY6 w0.121: v1(65.62,73.7) 66.23,74.31 87.16,74.31 87.35,74.12 88.81,74.12
  BOTTOM w0.121: J1.18 38.15,102.64 45.96,102.64 51.29,97.31 51.29,96.13 61.87,85.56 61.87,81.21 63.79,79.29 63.79,77.38 65.13,76.04 65.13,74.2 v1(65.62,73.7)
AM335X_RMII1_TXD2: length 85.5
  TOP w0.121: v2(91.33,75.12) U43.D3 ; v1(66.81,81.03) 68.86,81.03 68.99,80.9 v1(89.24,80.9)
  LY3 w0.102: v2(91.33,75.12) 90.92,75.12 90.52,75.52 89.34,75.52 88.94,75.92 88.94,78.65
  LY3 w0.121: 88.94,78.65 88.94,80.6 v1(89.24,80.9)
  LY6 w0.121: v1(53.36,110.52) 51.07,112.81 37.88,112.81 J1.12
  BOTTOM w0.121: v1(53.36,110.52) 53.36,96.48 62.73,87.11 62.73,85.49 65.02,83.21 65.02,81.26 65.78,80.5 66.27,80.5 v1(66.81,81.03)
AM335X_RMII1_TXD3: length 82.7
  TOP w0.102: 88.81,73.62 U43.E1
  TOP w0.121: v1(83.97,73.87) 84.41,73.87 84.75,74.21 87.59,74.21 88.17,73.62 88.81,73.62
  LY3 w0.121: v1(83.97,73.87) 80.45,77.39 80.45,102.04 80.21,102.29 v1(80.21,104.35)
  LY6 w0.121: v1(80.21,104.35) 59.71,104.35 58.46,105.6 37.73,105.6 J1.16
AM335X_RMII1_TXEN: length 99.4
  TOP w0.121: v1(121.26,93.33) 120.86,92.93 102,92.93 99.94,90.87 96.71,90.87 v1(95.16,92.42) ; J3.40 v1(124.12,139.61) ; v2(92.34,77.13) U43.B4
  LY3 w0.102: v2(92.34,77.13) 92.34,77.26 91.94,77.65 91.94,78.29 92.01,78.35 92.01,78.65
  LY3 w0.121: v1(90.73,83.8) 90.73,83.79 92.01,82.51 92.01,78.65
  BOTTOM w0.121: v1(121.26,93.33) 121.9,93.97 121.9,98.58 121.28,99.2 121.28,121.47 124.12,124.3 v1(124.12,139.61) ; v1(90.73,83.8) 91.7,83.8 92.01,84.11 94.88,84.11 95.84,85.08 95.84,87.82 95.16,88.51 v1(95.16,92.42)
AM335X_SPI0_CLK: length 82.6
  TOP w0.121: v2(97.34,77.13) U43.B9
  LY3 w0.121: J3.13 88.81,131.86 88.94,131.74 89.32,131.74 89.45,131.86 89.45,135.93 89.57,136.05 90.08,136.05 90.21,135.93 90.21,131.86 90.33,131.74 90.84,131.74 90.97,131.86 90.97,135.67 91.1,135.8 91.54,135.8 91.67,135.67 91.67,124.56 95.47,120.75 95.47,116.24 95.72,115.99 95.72,113.37 95.46,113.12 95.46,100.4 95.97,99.89 95.97,96.13 96.43,95.67 96.43,93 97.32,92.11 97.32,89.19 97.74,88.77 97.74,77.53 v2(97.34,77.13)
AM335X_SPI0_CS0: length 83.5
  TOP w0.121: v2(93.34,74.12) U43.E5 ; v1(63.83,82.63) U10.5
  LY3 w0.121: v1(65.57,74.59) 65.57,76.36 65.19,76.75 64.55,76.75 63.83,77.47 v1(63.83,82.63) 63.83,82.67 62.96,83.55 62.96,91.51 62.71,91.75 62.71,93.9 62.96,94.14 62.96,96.12 v1(62.65,96.43)
  LY6 w0.102: v2(93.34,74.12) 92.89,74.12 92.49,74.53 88.81,74.53
  LY6 w0.121: J1.24 35.47,96.43 35.34,96.3 35.34,95.64 35.57,95.41 59.47,95.41 60.49,96.43 v1(62.65,96.43) ; v1(65.57,74.59) 65.6,74.56 87.41,74.56 87.44,74.53 88.81,74.53
AM335X_SPI0_CS1: length 82.7
  TOP w0.121: v2(100.34,77.13) U43.B11
  LY3 w0.121: J3.17 93.89,132.55 94.02,132.42 94.68,132.42 94.8,132.55 94.8,135.93 94.93,136.05 95.58,136.05 95.7,135.93 95.7,131.86 95.58,131.74 94.19,131.74 94.07,131.61 94.07,131.18 94.19,131.05 97.6,131.05 97.73,130.92 97.73,130.57 97.6,130.44 94.02,130.44 93.89,130.31 93.89,124.13 94.15,123.86 96.18,123.86 96.77,123.27 96.77,117.91 97.26,117.42 97.26,103.61 96.86,103.21 96.86,102.4 97.07,102.19 97.07,97.48 97.53,97.02 97.53,93.68 98.49,92.72 98.49,90.08 98.89,89.67 98.89,77.92 99.13,77.68 99.78,77.68 v2(100.34,77.13)
AM335X_SPI0_D0: length 82.9
  TOP w0.121: v2(99.34,77.13) U43.B10
  LY3 w0.121: J3.15 91.99,137.71 92.24,137.71 92.37,137.58 92.37,129.32 92.49,129.2 92.87,129.2 93,129.32 93,135.8 93.13,135.93 93.45,135.93 93.57,135.8 93.57,127.29 93.45,127.16 92.11,127.16 91.99,127.04 91.99,126.78 92.11,126.66 93.45,126.66 93.57,126.53 93.57,125.2 93,124.62 93,123.74 95.87,120.86 95.87,118.45 97.01,117.31 97.01,103.71 96.61,103.31 96.61,102.29 96.81,102.1 96.81,97.36 97.28,96.89 97.28,93.55 98.16,92.67 98.16,89.85 98.59,89.42 98.59,77.87 v2(99.34,77.13)
AM335X_SPI0_D1: length 84.7
  TOP w0.121: v2(94.34,72.13) U43.G6 ; v1(63.12,82.63) U10.4
  LY3 w0.121: v1(64.69,74.65) 64.69,76.23 63.54,77.38 63.54,82.21 v1(63.12,82.63) 62.71,83.03 62.71,91.41 62.47,91.65 62.47,94 62.52,94.05 v1(62.52,95.27)
  LY6 w0.102: v2(94.34,72.13) 93.73,72.73 93.73,74.37 93.36,74.73 88.92,74.73 88.81,74.84
  LY6 w0.121: J1.23 35.6,95.03 59.97,95.03 60.24,95.29 62.49,95.29 v1(62.52,95.27) ; 88.81,74.84 66.46,74.84 66.27,75.03 65.06,75.03 v1(64.69,74.65)
AM335X_TSC_CLK: length 62.2
  TOP w0.121: v2(95.34,62.12) U43.T7
  LY3 w0.102: 90.84,59.6 90.84,61.25 91.11,61.52 91.49,61.52 91.73,61.76 91.73,62.12 92.13,62.52 94.52,62.52 94.92,62.12 v2(95.34,62.12)
  LY3 w0.121: 90.84,59.6 90.84,58.58 89.7,57.44 89.7,50.45 v1(90.59,49.56)
  BOTTOM w0.121: J7.5 122.29,61.12 122.54,60.87 122.54,52.17 121.72,51.34 117.25,51.34 116.56,52.04 93.32,52.04 90.84,49.56 v1(90.59,49.56)
AM335X_TSC_GIO0: length 56.6
  TOP w0.121: v2(93.34,62.12) U43.T5
  LY3 w0.102: 92.5,59.35 92.5,60.53 92.73,60.77 92.73,61.52 v2(93.34,62.12)
  LY3 w0.121: v1(91.48,48.68) 91.48,49.82 90.21,51.09 90.21,57.06 92.5,59.35
  LY6 w0.121: J7.1 121.45,64.17 121.31,64.31 119.69,64.31 119.31,63.93 119.31,61.63 116.14,58.45 107.09,58.45 106.08,57.44 106.08,53.52 101.57,49.02 91.81,49.02 v1(91.48,48.68)
AM335X_TSC_GIO1: length 52.3
  TOP w0.121: v2(94.34,62.12) U43.T6
  LY6 w0.102: v2(94.34,62.12) 94.75,62.12 95.15,62.52 96.33,62.52 96.73,62.92 96.73,68.11 99.14,70.52 102.53,70.52 102.73,70.32 102.73,70.12 103.34,69.51 104.94,69.51 104.98,69.47 107.39,69.47 107.86,69.94
  LY6 w0.121: J7.3 125.13,62.39 126.91,64.17 126.91,69 125.6,70.31 110.33,70.31 109.96,69.94 107.86,69.94
AM335X_TSC_GIO2: length 27.3
  TOP w0.121: v2(99.34,62.12) U43.T10
  BOTTOM w0.102: 101.26,59.6 100.73,60.13 100.73,60.29 100.5,60.52 100.34,60.52 99.73,61.12 99.73,61.73 v2(99.34,62.12)
  BOTTOM w0.121: 101.26,59.6 101.89,58.97 105.57,58.97 105.94,58.6 105.94,57.19 107.53,55.6 113.97,55.6 118.23,59.85 120.18,59.85
AM335X_TSC_RSV0: length 3.1
  TOP w0.121: J7.7 122.85,59.85 123.23,60.24 TP4.1
AM335X_TSC_RSV1_VREF: length 3
  TOP w0.121: J7.9 123.1,58.58 123.35,58.33 TP5.1
AM335X_UART0_CTSN: length 69.1
  TOP w0.121: v2(102.33,77.13) U43.B13
  LY6 w0.121: J3.21 98.97,122.99 98.33,122.35 98.33,118.33 v1(101.51,115.15)
  BOTTOM w0.102: 106.95,78.65 106.95,78.41 106.73,78.19 106.73,77.93 106.33,77.53 103.16,77.53 102.75,77.13 v2(102.33,77.13) ; 101.51,103.01 101.55,102.97 101.55,100.51 101.84,100.22 101.84,96.56 102.48,95.92 103.54,95.92 104.18,95.29 104.18,94.77 104.74,94.21
  BOTTOM w0.121: 104.74,94.21 106.71,92.24 106.71,80.17 106.95,79.94 106.95,78.65 ; v1(101.51,115.15) 101.51,103.01
AM335X_UART0_RTSN: length 78.2
  TOP w0.121: v2(103.33,77.13) U43.B14
  LY6 w0.102: v2(103.33,77.13) 103.33,78.65
  LY6 w0.121: J3.23 101.51,124.3 102.15,123.66 106.76,123.66 v1(107.41,123.01) ; 103.33,78.65 103.33,79.04 103.07,79.31 103.06,79.31 102.97,79.4 102.97,82.77 104.37,84.17 105.78,84.17 107.01,85.41 v1(111.8,85.41)
  BOTTOM w0.121: v1(111.8,85.41) 110.81,86.39 110.81,96.34 111.16,96.68 111.16,106.22 112.24,107.3 112.24,108.11 112.17,108.18 112.17,121.62 110.77,123.01 v1(107.41,123.01)
AM335X_UART0_RXD: length 112.5
  TOP w0.121: v2(104.33,77.13) U43.B15
  LY3 w0.121: v1(126.14,85.57) 126.14,113.33 123.35,116.12 123.35,140.75 123.23,140.88 105.44,140.88 105.32,140.76 105.32,138.34 J3.25
  LY6 w0.102: 102.94,78.65 102.94,76.96 103.17,76.73 103.5,76.73 103.89,77.13 v2(104.33,77.13)
  LY6 w0.121: v1(126.14,85.57) 125.77,85.21 113.95,85.21 113.27,85.89 105.04,85.89 102.73,83.57 102.73,79.17 102.94,78.96 102.94,78.65
AM335X_UART0_TXD: length 72.1
  TOP w0.121: v2(105.34,77.13) U43.B16 ; v1(106.95,113.04) v1(113.89,113.04)
  LY3 w0.102: 107.5,97.72 107.13,97.35 107.13,94.21 ; v2(105.34,77.13) 105.34,77.54 105.74,77.95 105.74,78.65
  LY3 w0.121: v1(106.95,113.04) 107.33,112.66 107.33,108.57 106.95,108.2 106.95,103.3 107.61,102.65 107.61,97.83 107.5,97.72 ; 105.74,78.65 105.74,81.47 105.76,81.49 105.76,92.37 107.13,93.73 107.13,94.21
  LY6 w0.121: J3.27 113.89,129.77 v1(113.89,123.23)
  BOTTOM w0.121: v1(113.89,113.04) v1(113.89,123.23)
AM335X_UART1_CTSN: length 145.3
  TOP w0.102: v2(107.34,77.13) 107.86,77.65
  TOP w0.121: v2(107.34,77.13) U43.B18 ; v1(114.21,87.35) 114.19,87.35 113.63,86.79 113.63,82.38 113,81.74 110.89,81.74 109.73,80.58 109.19,80.58 108.11,79.5 108.11,77.9 107.86,77.65 ; v1(60.49,77.76) 60.74,78.02 61.8,78.02 U11.4
  LY3 w0.121: v1(77.76,76.87) 77.76,80.75 76.94,81.57 v1(76.94,86.85)
  LY6 w0.121: v1(76.94,86.85) 81.08,86.85 81.26,86.67 90.36,86.67 91.34,87.66 113.89,87.66 v1(114.21,87.35) 114.27,87.29 120.08,87.29 122.78,89.99 122.78,102.26 120.92,104.13 120.92,110.76 117.91,113.77 117.91,121.45 114.22,125.13 114.22,131.98 J3.29 ; v1(60.49,77.76) 64.05,77.76 64.93,76.87 65.7,76.87 65.95,77.13 69,77.13 69.25,76.87 v1(77.76,76.87)
AM335X_UART1_RTSN: length 117.5
  TOP w0.121: v1(90.17,79.76) 83.16,79.76 83.07,79.85 v1(82.63,79.85) 75.73,79.85 74.93,80.65 70.36,80.65 69.76,80.05 69.76,78.02 69.17,77.43 v1(65.24,77.43) U11.5 ; v2(92.34,76.13) U43.C4
  LY3 w0.121: J3.31 109.69,135.09 106.53,135.09 104.05,132.61 v1(104.05,130.79)
  LY6 w0.102: 92.73,78.65 92.73,76.96 92.34,76.57 v2(92.34,76.13)
  LY6 w0.121: v1(90.17,79.76) 90.8,79.13 92.25,79.13 92.73,78.65
  BOTTOM w0.121: v1(104.05,130.79) 85.57,130.79 84.04,129.26 84.04,124.12 83.79,123.86 83.79,113.71 81.76,111.69 81.76,88.14 82.34,87.56 82.34,82.41 82.63,82.13 v1(82.63,79.85)
AM335X_UART1_RXD: length 81.1
  TOP w0.121: v2(93.34,76.13) U43.C5
  LY3 w0.102: v2(93.34,76.13) 93.93,76.72 93.93,78.06 93.85,78.14 93.85,78.65
  LY3 w0.121: 93.85,78.65 93.85,85.17 93.84,85.18 93.84,103.72 93.64,103.92 93.64,117.77 94.14,118.27 v1(94.15,118.27)
  LY6 w0.121: J3.33 113.26,138.02 98.53,138.02 97.96,137.45 97.96,134.16 94.15,130.35 v1(94.15,118.27)
AM335X_UART1_TXD: length 93
  TOP w0.121: v2(94.34,76.13) U43.C6
  LY3 w0.121: J3.35 121.2,132.63 121.2,122.01 v1(121.07,121.88) ; v1(92.87,89) 92.87,87.98 91.72,86.82 v1(91.72,84.85)
  LY6 w0.102: v2(94.34,76.13) 94.78,76.13 95.17,75.73 95.5,75.73 95.73,75.96 95.73,78.38 95.69,78.41 95.69,78.65
  LY6 w0.121: 95.69,78.65 95.69,78.9 93.39,81.21 93.03,81.21 91.76,82.48 91.76,84.7 91.72,84.74 v1(91.72,84.85) ; v1(92.87,89) 101.76,89 105.95,93.18 119.75,93.18 120.71,94.14 120.71,97.44 v1(121.45,98.18)
  BOTTOM w0.121: v1(121.45,98.18) 121.45,98.46 121.03,98.88 121.03,121.7 121.07,121.74 v1(121.07,121.88)
AM335X_WAKEUP: length 168.5
  TOP w0.102: 95.8,78.65 95.84,78.61 U43.A7
  TOP w0.121: 95.8,78.65 95.29,79.16 94.91,79.16 94.9,79.16 92.49,79.16 90.31,81.34 v1(69.62,81.34) ; U42.6 64.82,25.33 65.06,25.56 v1(65.06,25.95) R126.1
  LY3 w0.121: v1(69.06,129.89) 69.06,129.44 69.26,129.24 69.26,108.12 69.76,107.62 69.76,90.57 70.2,90.14 70.2,89.77 69.62,89.19 v1(69.62,81.34) 69.62,70.38 66.25,67.01 66.24,67.01 64.65,65.43 64.65,64.77 64.48,64.6 64.48,64.23 64.65,64.06 64.65,30.23 63.92,29.5 63.92,27.09 v1(65.06,25.95)
  LY6 w0.121: J3.18 92.8,138.52 92.8,137.14 89.12,133.45 72.63,133.45 v1(69.06,129.89)
AM335X_XDMA_EVENT_INTR0: length 101.9
  TOP w0.102: U43.A14 102.83,78.65
  TOP w0.121: 102.83,78.65 102.83,80.73 104.68,82.57 v1(113.19,82.57)
  LY6 w0.121: v1(113.19,82.57) 114.73,84.1 125.31,84.1 126.94,85.74 126.94,96.68 127.16,96.9 127.16,99.1 126.94,99.32 126.94,136.62 125.23,138.33 107.87,138.33 J3.28
